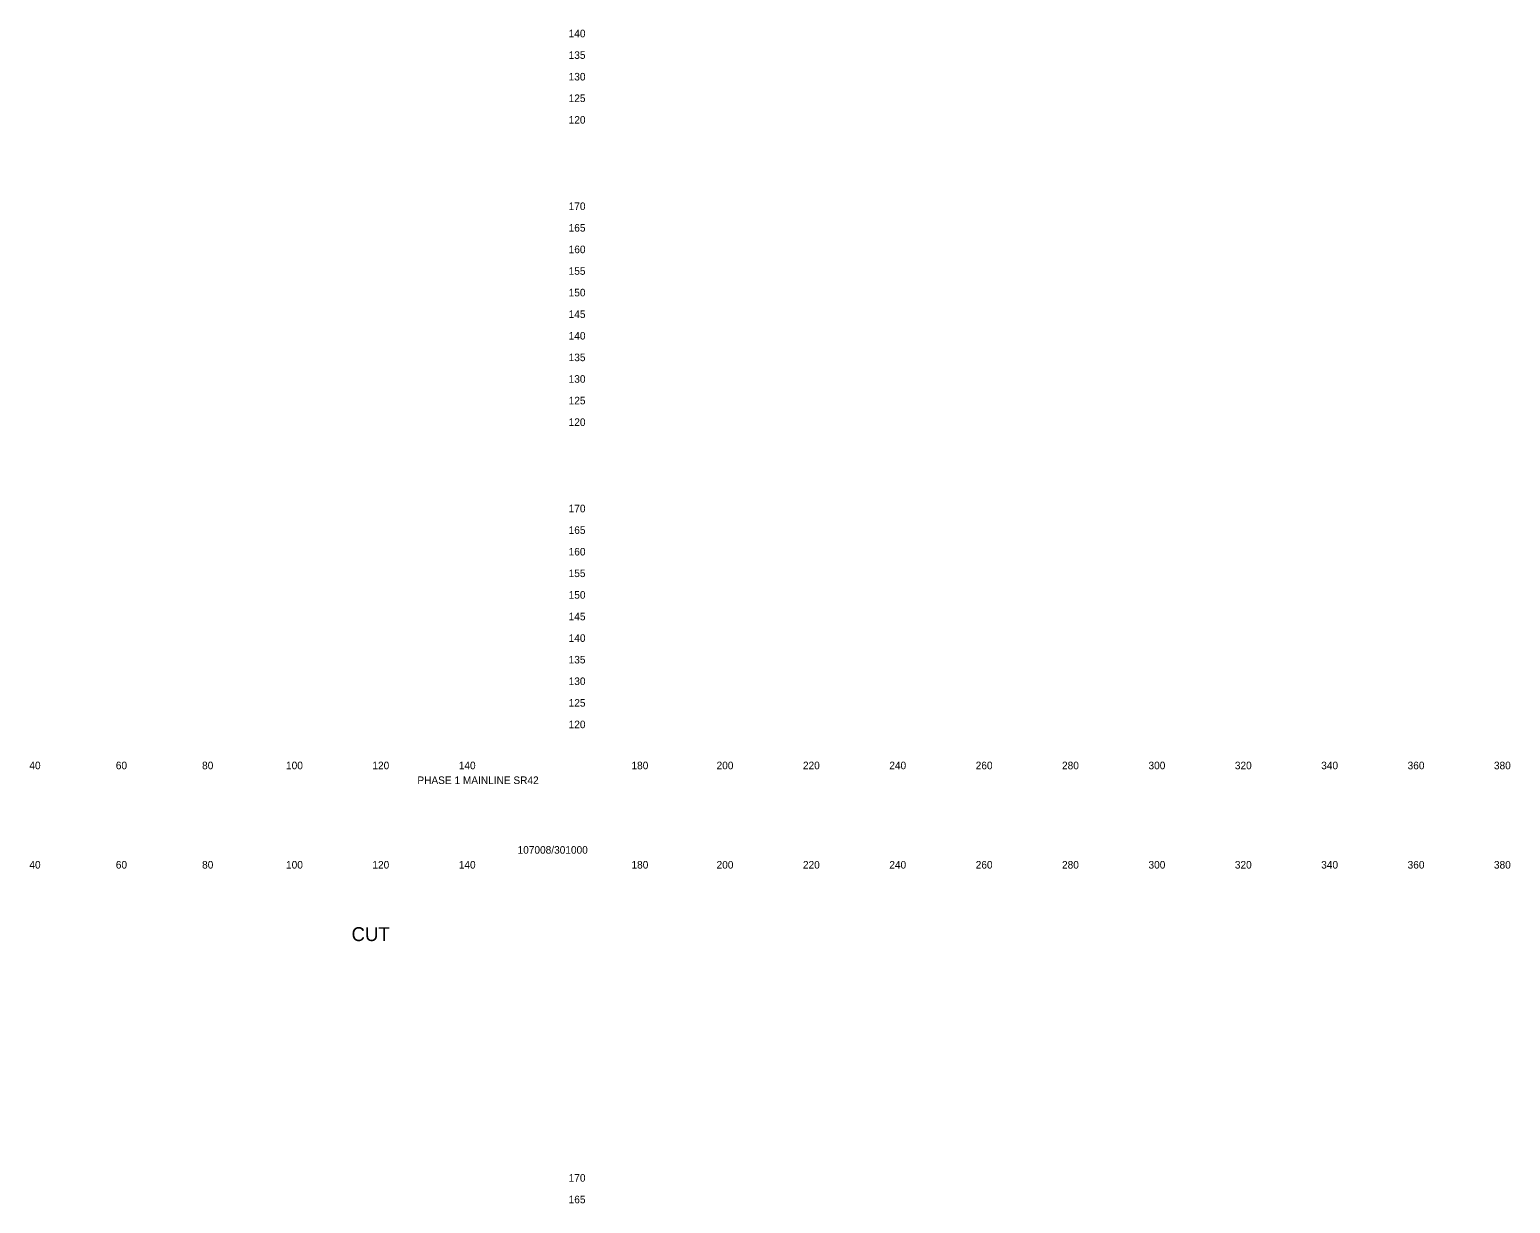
# Model space of a CAD drawing. Extents: x 21281 to 22024, y 6472 to 15198.
# Drawn here: x 21681.3 to 22024.2, y 14654.8 to 14926.6 of the extents above; entities that cross this region are included whole.
import ezdxf

# ---------------------------------------------------------------- set-up
doc = ezdxf.new("R2010")
doc.units = 0
doc.layers.add('XS_SHEET_LABELS_ELEVATION', color=7, linetype='Continuous')
doc.layers.add('XS_SHEET_LABELS_OFFSET', color=7, linetype='Continuous')

msp = doc.modelspace()

# ---------------------------------------------------------------- texts
at = {"layer": 'XS_SHEET_LABELS_ELEVATION'}
for s, p in [('  140  ', (21804.84, 14924.84)), ('  135  ', (21804.84, 14919.84)), ('  130  ', (21804.84, 14914.84)), ('  125  ', (21804.84, 14909.84)), ('  120  ', (21804.84, 14904.84)), ('  170  ', (21804.84, 14884.84)), ('  165  ', (21804.84, 14879.84)), ('  160  ', (21804.84, 14874.84)), ('  155  ', (21804.84, 14869.84)), ('  150  ', (21804.84, 14864.84)), ('  145  ', (21804.84, 14859.84)), ('  140  ', (21804.84, 14854.84)), ('  135  ', (21804.84, 14849.84)), ('  130  ', (21804.84, 14844.84)), ('  125  ', (21804.84, 14839.84)), ('  120  ', (21804.84, 14834.84)), ('  170  ', (21804.84, 14814.84)), ('  165  ', (21804.84, 14809.84)), ('  160  ', (21804.84, 14804.84)), ('  155  ', (21804.84, 14799.84)), ('  150  ', (21804.84, 14794.84)), ('  145  ', (21804.84, 14789.84)), ('  140  ', (21804.84, 14784.84)), ('  135  ', (21804.84, 14779.84)), ('  130  ', (21804.84, 14774.84)), ('  125  ', (21804.84, 14769.84)), ('  120  ', (21804.84, 14764.84)), ('  170  ', (21804.84, 14659.84)), ('  165  ', (21804.84, 14654.84))]:
    msp.add_text(s, height=1.75, dxfattribs=at).set_placement(p)
at = {"layer": 'XS_SHEET_LABELS_OFFSET'}
for s, height, p in [('  40  ', 1.75, (21679.95, 14755.34)), ('  60  ', 1.75, (21699.97, 14755.34)), ('  80  ', 1.75, (21719.95, 14755.34)), ('  100  ', 1.75, (21739.39, 14755.34)), ('  120  ', 1.75, (21759.39, 14755.34)), ('  140  ', 1.75, (21779.39, 14755.34)), ('  180  ', 1.75, (21819.39, 14755.34)), ('  200  ', 1.75, (21839.1, 14755.34)), ('  220  ', 1.75, (21859.1, 14755.34)), ('  240  ', 1.75, (21879.1, 14755.34)), ('  260  ', 1.75, (21899.11, 14755.34)), ('  280  ', 1.75, (21919.1, 14755.34)), ('  300  ', 1.75, (21939.13, 14755.34)), ('  320  ', 1.75, (21959.13, 14755.34)), ('  340  ', 1.75, (21979.13, 14755.34)), ('  360  ', 1.75, (21999.14, 14755.34)), ('  380  ', 1.75, (22019.13, 14755.34)), ('PHASE 1 MAINLINE SR42', 1.75, (21771.11, 14751.92)), ('107008/301000', 1.75, (21794.31, 14735.79)), ('  40  ', 1.75, (21679.95, 14732.34)), ('  60  ', 1.75, (21699.97, 14732.34)), ('  80  ', 1.75, (21719.95, 14732.34)), ('  100  ', 1.75, (21739.39, 14732.34)), ('  120  ', 1.75, (21759.39, 14732.34)), ('  140  ', 1.75, (21779.39, 14732.34)), ('  180  ', 1.75, (21819.39, 14732.34)), ('  200  ', 1.75, (21839.1, 14732.34)), ('  220  ', 1.75, (21859.1, 14732.34)), ('  240  ', 1.75, (21879.1, 14732.34)), ('  260  ', 1.75, (21899.11, 14732.34)), ('  280  ', 1.75, (21919.1, 14732.34)), ('  300  ', 1.75, (21939.13, 14732.34)), ('  320  ', 1.75, (21959.13, 14732.34)), ('  340  ', 1.75, (21979.13, 14732.34)), ('  360  ', 1.75, (21999.14, 14732.34)), ('  380  ', 1.75, (22019.13, 14732.34)), ('CUT', 3.222, (21755.86, 14715.55))]:
    msp.add_text(s, height=height, dxfattribs=at).set_placement(p)

doc.saveas('drawing.dxf')
